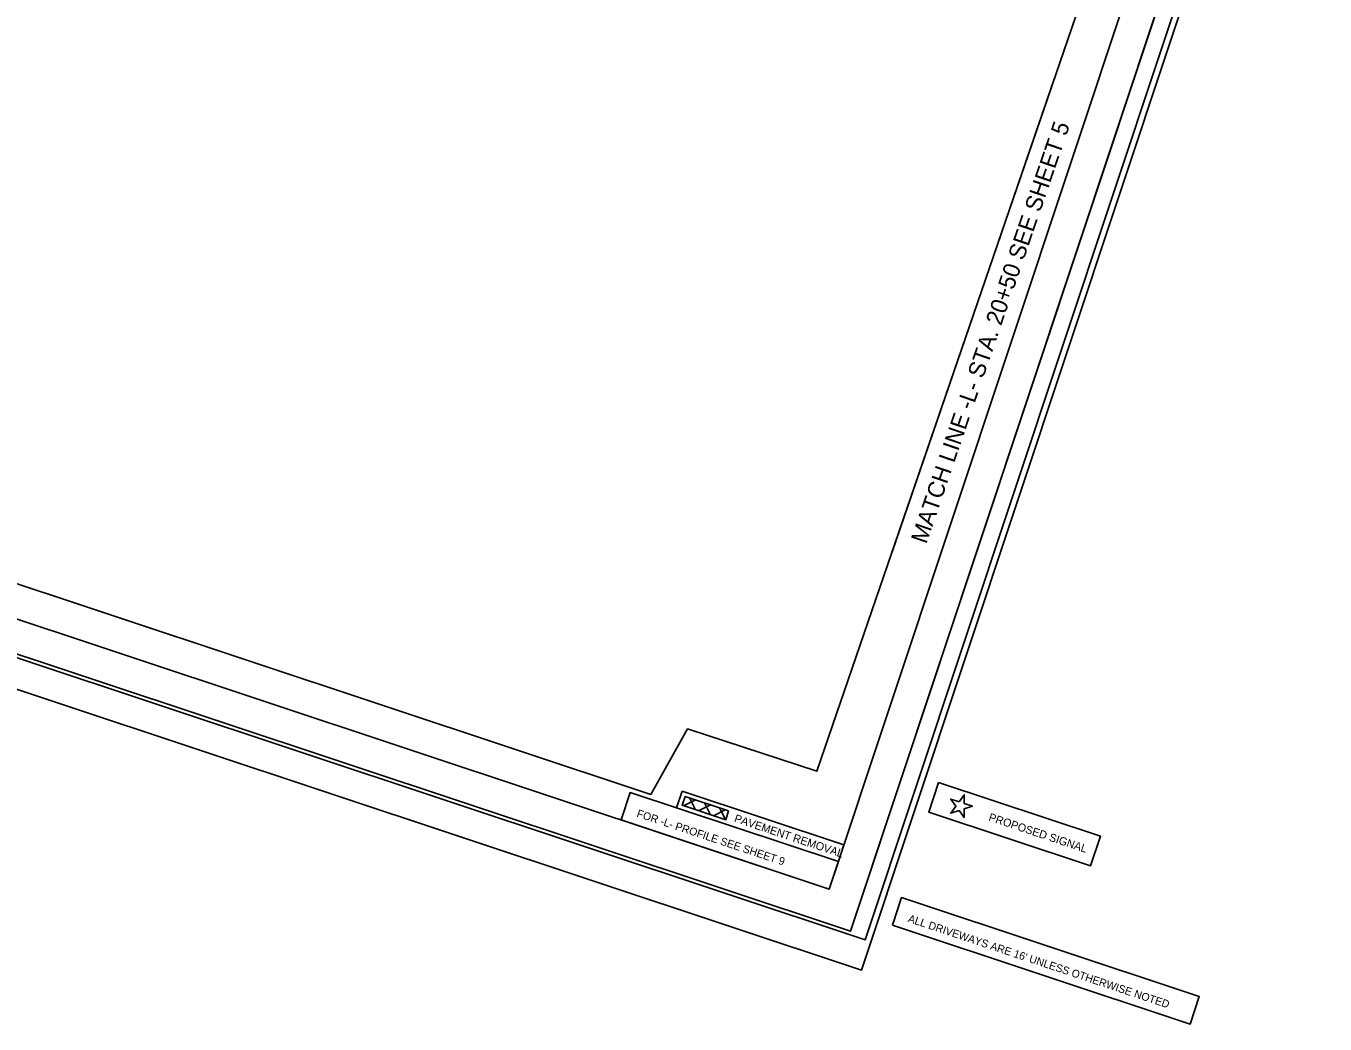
# Model space of a CAD drawing. Extents: x 2296288 to 2297455, y 600637 to 601606.
# Drawn here: x 2296872 to 2297455, y 600637 to 601085 of the extents above; entities that cross this region are included whole.
import ezdxf

# ---------------------------------------------------------------- set-up
doc = ezdxf.new("R2010")
doc.units = 0
for name, color, linetype in [('COGO Default Point Elevation', 7, 'Continuous'), ('COGO Default Point Number', 7, 'Continuous'), ('Default', 7, 'Continuous'), ('Exist DTM Drainline Cogo Comment', 7, 'Continuous'), ('Exist DTM Drainline Cogo Elevation', 7, 'Continuous'), ('Exist DTM Drainline Cogo Number', 7, 'Continuous'), ('Exist DTM Drainline Cogo Point CELL', 7, 'Continuous'), ('Exist Property Iron Pin Cogo Number', 7, 'Continuous'), ('Exist Roads Curbs Cogo Elevation', 7, 'Continuous'), ('Exist Roads Curbs Cogo Number', 7, 'Continuous'), ('Exist Roads Curbs Cogo Point CELL', 7, 'Continuous'), ('Exist Roads EOP Cogo Comment', 7, 'Continuous'), ('Exist Roads EOP Cogo Elevation', 7, 'Continuous')]:
    doc.layers.add(name, color=color, linetype=linetype)

msp = doc.modelspace()

# ---------------------------------------------------------------- linework, layer by layer
at = {"layer": 'COGO Default Point Elevation'}
msp.add_line((2297260.53, 600848.69), (2297333.49, 601061.53), dxfattribs=at)
at = {"layer": 'Default'}
for p, q in [((2297166.9, 600734.65), (2297172.23, 600737.32)), ((2297169.57, 600738.21), (2297172.25, 600732.87)), ((2297173.6, 600732.42), (2297178.93, 600735.09)), ((2297176.29, 600735.97), (2297178.96, 600730.63)), ((2297180.3, 600730.18), (2297185.63, 600732.85)), ((2297183, 600733.73), (2297185.67, 600728.39))]:
    msp.add_line(p, q, dxfattribs=at)
for points in [[(2297166.21, 600741.23), (2297238.93, 600717.06), (2297236.43, 600709.55), (2297163.72, 600733.73)], [(2297187.13, 600732.35), (2297167.63, 600738.86), (2297166.29, 600734.86), (2297185.8, 600728.35)]]:
    msp.add_lwpolyline(points, close=True, dxfattribs=at)
at = {"layer": 'Exist DTM Drainline Cogo Comment'}
msp.add_lwpolyline([(2297440.6, 601276.06), (2296586.57, 601560.02), (2296387.8, 600962.2), (2297241.83, 600678.24)], close=True, dxfattribs=at)
at = {"layer": 'Exist DTM Drainline Cogo Elevation'}
msp.add_lwpolyline([(2297290.64, 600736.4), (2297286.93, 600737.63), (2297289.21, 600734.45), (2297286.89, 600731.29), (2297290.62, 600732.48), (2297292.9, 600729.3), (2297292.93, 600733.21), (2297296.66, 600734.4), (2297292.95, 600735.63), (2297292.97, 600739.55), (2297290.64, 600736.4)], dxfattribs=at)
at = {"layer": 'Exist DTM Drainline Cogo Number'}
msp.add_lwpolyline([(2297281.45, 600745.15), (2297354.17, 600720.97), (2297349.74, 600707.62), (2297277.01, 600731.81)], close=True, dxfattribs=at)
at = {"layer": 'Exist DTM Drainline Cogo Point CELL'}
msp.add_lwpolyline([(2297421.64, 601266.56), (2296596.08, 601541.06), (2296406.77, 600971.7), (2297232.33, 600697.21)], close=True, dxfattribs=at)
at = {"layer": 'Exist Property Iron Pin Cogo Number'}
msp.add_lwpolyline([(2296425.75, 600981.21), (2297152.11, 600739.71), (2297168.67, 600769.15), (2297226.75, 600750.14), (2297369.4, 601166.29), (2297286.75, 601193.77), (2297317.24, 601285.47), (2296605.59, 601522.09)], close=True, dxfattribs=at)
at = {"layer": 'Exist Roads Curbs Cogo Elevation'}
msp.add_lwpolyline([(2296586.57, 601560.02), (2296387.82, 600962.21), (2297241.85, 600678.25), (2297402.77, 601162.3), (2297288.88, 601200.18), (2297326.7, 601313.93)], close=True, dxfattribs=at)
at = {"layer": 'Exist Roads Curbs Cogo Number'}
msp.add_lwpolyline([(2297455.02, 601287.08), (2296496.23, 601605.87), (2296287.99, 600979.58), (2297246.78, 600660.79)], close=True, dxfattribs=at)
at = {"layer": 'Exist Roads Curbs Cogo Point CELL'}
msp.add_lwpolyline([(2297448.2, 601275.15), (2296499.38, 601590.63), (2296299.64, 600989.9), (2297248.47, 600674.42)], close=True, dxfattribs=at)
at = {"layer": 'Exist Roads EOP Cogo Elevation'}
for points in [[(2297138.84, 600728.29), (2297232.33, 600697.21), (2297236.43, 600709.55), (2297142.94, 600740.64)], [(2297260.67, 600681.07), (2297394.45, 600636.59), (2297398.55, 600648.93), (2297264.78, 600693.41)]]:
    msp.add_lwpolyline(points, close=True, dxfattribs=at)

# ---------------------------------------------------------------- texts
at = {"layer": 'COGO Default Point Number'}
msp.add_text('MATCH LINE -L- STA. 20+50 SEE SHEET 5', height=7.5, rotation=71.0791, dxfattribs=at).set_placement((2297275.91, 600851.93))
at = {"layer": 'Exist Roads EOP Cogo Comment'}
for s, height, rotation, p in [('FOR -L- PROFILE SEE SHEET 9', 3.5, 341.60824, (2297145.54, 600729.76)), ('PAVEMENT REMOVAL', 3.5953, 341.55035, (2297189.33, 600727.51)), ('PROPOSED SIGNAL', 3.5953, 341.60824, (2297303.62, 600728.04)), ("ALL DRIVEWAYS ARE 16' UNLESS OTHERWISE NOTED", 3.5, 341.60824, (2297267.38, 600682.53))]:
    msp.add_text(s, height=height, rotation=rotation, dxfattribs=at).set_placement(p)

doc.saveas('drawing.dxf')
